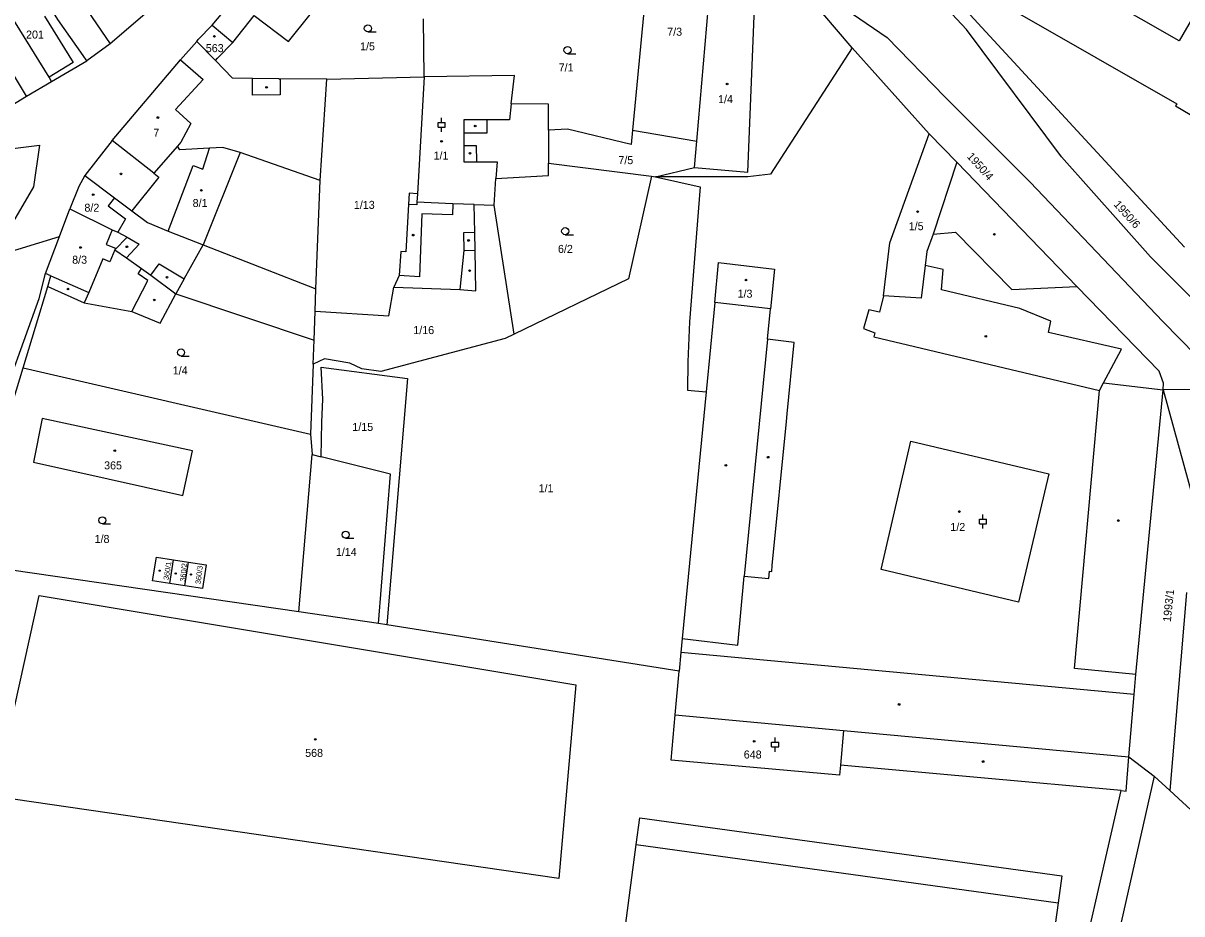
# Model space of a CAD drawing. Extents: x -794765 to -785424, y -1118958 to -1108731.
# Drawn here: x -788278.3 to -788032.3, y -1116985.8 to -1116796.6 of the extents above; entities that cross this region are included whole.
import ezdxf

# ---------------------------------------------------------------- set-up
doc = ezdxf.new("R2010")
doc.units = 0
for name, color, linetype in [('Level 66', 7, 'Continuous'), ('Level 75', 7, 'Continuous'), ('Level 76', 7, 'Continuous'), ('Level 77', 7, 'Continuous'), ('Level 79', 7, 'Continuous')]:
    doc.layers.add(name, color=color, linetype=linetype)

msp = doc.modelspace()

# ---------------------------------------------------------------- linework, layer by layer
at = {"layer": 'Level 66'}
for p, q in [((-788205.14, -1116798.45), (-788203.39, -1116798.45)), ((-788162.74, -1116803.07), (-788160.99, -1116803.07)), ((-788189.48, -1116817.69), (-788189.48, -1116816.69)), ((-788190.23, -1116817.69), (-788188.73, -1116817.69)), ((-788190.23, -1116818.69), (-788190.23, -1116817.69)), ((-788190.23, -1116818.69), (-788188.73, -1116818.69)), ((-788189.48, -1116819.69), (-788189.48, -1116818.69)), ((-788188.73, -1116818.69), (-788188.73, -1116817.69)), ((-788163.24, -1116841.52), (-788161.49, -1116841.52)), ((-788244.8, -1116867.29), (-788243.05, -1116867.29)), ((-788074.53, -1116901.92), (-788074.53, -1116900.92)), ((-788261.5, -1116902.94), (-788259.75, -1116902.94)), ((-788075.28, -1116901.92), (-788073.78, -1116901.92)), ((-788075.28, -1116902.92), (-788075.28, -1116901.92)), ((-788075.28, -1116902.92), (-788073.78, -1116902.92)), ((-788074.53, -1116903.92), (-788074.53, -1116902.92)), ((-788073.78, -1116902.92), (-788073.78, -1116901.92)), ((-788209.86, -1116905.99), (-788208.11, -1116905.99)), ((-788119.4, -1116949.33), (-788117.9, -1116949.33)), ((-788119.4, -1116950.33), (-788119.4, -1116949.33)), ((-788119.4, -1116950.33), (-788117.9, -1116950.33)), ((-788118.65, -1116949.33), (-788118.65, -1116948.33)), ((-788118.65, -1116951.33), (-788118.65, -1116950.33)), ((-788117.9, -1116950.33), (-788117.9, -1116949.33))]:
    msp.add_line(p, q, dxfattribs=at)
for centre in [(-788205.14, -1116797.7), (-788162.74, -1116802.32), (-788163.24, -1116840.77), (-788244.8, -1116866.54), (-788261.5, -1116902.19), (-788209.86, -1116905.24)]:
    msp.add_circle(centre, 0.75, dxfattribs=at)
at = {"layer": 'Level 75'}
for p, q in [((-788102.31, -1116801.86), (-788122.75, -1116777.73)), ((-788238.21, -1116796.99), (-788224.89, -1116781.19)), ((-788086.56, -1116784.66), (-788031.75, -1116844.15)), ((-788135.27, -1116821.65), (-788132.81, -1116792.93)), ((-788238.21, -1116796.99), (-788233.82, -1116800.7)), ((-788193.21, -1116808), (-788193.34, -1116795.7)), ((-788237.52, -1116804.54), (-788241.47, -1116800.45)), ((-788102.31, -1116801.86), (-788119.65, -1116828.64)), ((-788085.95, -1116820.1), (-788102.31, -1116801.86)), ((-788272.28, -1116808.99), (-788264.8, -1116804.59)), ((-788215.23, -1116830.01), (-788213.88, -1116808.51)), ((-788213.88, -1116808.51), (-788193.21, -1116808)), ((-788166.76, -1116819.32), (-788166.76, -1116826.32)), ((-788148.95, -1116819.33), (-788135.27, -1116821.65)), ((-788259.4, -1116821.53), (-788265.21, -1116828.93)), ((-788080.11, -1116826.14), (-788085.95, -1116820.1)), ((-788166.76, -1116826.32), (-788144.9, -1116829.12)), ((-788144.9, -1116829.12), (-788144.03, -1116829.23)), ((-788124.47, -1116829.22), (-788144.03, -1116829.23)), ((-788119.65, -1116828.64), (-788124.47, -1116829.22)), ((-788216.17, -1116853), (-788215.23, -1116830.01)), ((-788270.62, -1116841.89), (-788268.43, -1116836.01)), ((-788174.1, -1116862.62), (-788178.35, -1116835.27)), ((-788284.93, -1116846.27), (-788270.62, -1116841.89)), ((-788273.57, -1116849.78), (-788270.62, -1116841.89)), ((-788278.3, -1116869.83), (-788273.09, -1116852.5)), ((-788245.9, -1116854.09), (-788216.56, -1116863.93)), ((-788216.34, -1116857.79), (-788216.17, -1116853)), ((-788216.56, -1116863.93), (-788216.34, -1116857.79)), ((-788216.76, -1116869.03), (-788216.56, -1116863.93)), ((-788216.76, -1116869.03), (-788217.35, -1116883.92)), ((-788284.57, -1116890.25), (-788278.3, -1116869.83)), ((-788278.3, -1116869.83), (-788217.35, -1116883.92)), ((-788022.19, -1116874.41), (-788036.25, -1116874.48)), ((-788036.25, -1116874.48), (-788029.67, -1116898.48)), ((-788217.35, -1116883.92), (-788216.97, -1116888.2)), ((-788219.76, -1116921.65), (-788216.97, -1116888.2)), ((-788216.97, -1116888.2), (-788215.03, -1116888.69)), ((-788247.21, -1116915.61), (-788246.4, -1116910.57)), ((-788246.4, -1116910.57), (-788243.2, -1116911.06)), ((-788244, -1116916.09), (-788243.2, -1116911.06)), ((-788219.76, -1116921.65), (-788280.81, -1116912.75)), ((-788244, -1116916.09), (-788247.21, -1116915.61)), ((-788031.28, -1116917.52), (-788034.85, -1116959.6)), ((-788202.9, -1116924.1), (-788219.76, -1116921.65)), ((-788201.1, -1116924.39), (-788202.9, -1116924.1)), ((-788139.02, -1116934.24), (-788201.1, -1116924.39)), ((-788139.86, -1116943.51), (-788139.02, -1116934.24)), ((-788043.54, -1116952.39), (-788038.17, -1116956.55)), ((-788038.17, -1116956.55), (-788075.38, -1117120.72)), ((-788034.85, -1116959.6), (-788038.17, -1116956.55)), ((-788034.85, -1116959.6), (-788007.01, -1116985.23))]:
    msp.add_line(p, q, dxfattribs=at)
for points in [[(-787892.56, -1116976.99), (-787895.19, -1116981.23), (-787941.8, -1116937.65), (-788018.27, -1116866.79), (-788038.98, -1116846.21), (-788057.86, -1116825), (-788078.06, -1116797.96), (-788091.43, -1116783.54), (-788101.65, -1116776.74), (-788123.35, -1116751.89), (-788142.7, -1116729.68), (-788154.86, -1116714.68), (-788158.83, -1116708.96), (-788160.26, -1116705.12), (-788161.73, -1116697.18), (-788161.16, -1116678.39), (-788158.78, -1116640.39), (-788158.44, -1116620.71), (-788158.79, -1116611.56), (-788160.53, -1116602.53)], [(-788067.75, -1116794.03), (-788033.39, -1116813.75), (-788033.67, -1116814.13), (-788027.08, -1116818.05), (-788023.52, -1116820.1), (-788021.63, -1116816.78), (-788019.77, -1116813.56), (-788015.67, -1116816), (-788014.58, -1116816.6), (-788011.36, -1116810.96), (-788011.98, -1116810.6), (-788004.49, -1116797.7), (-788002.85, -1116798.65), (-787998.57, -1116791.26), (-788020.48, -1116778.64), (-788030.53, -1116772.85), (-788034.34, -1116779.51), (-788061.85, -1116783.73), (-788067.75, -1116794.03)], [(-788168.06, -1116778.04), (-788159.81, -1116778.04), (-788147.84, -1116782.59), (-788145.53, -1116783.68), (-788148.95, -1116819.33)], [(-788121.73, -1116777.04), (-788119.47, -1116776.79), (-788115.27, -1116779.69), (-788102.26, -1116794.62), (-788094.84, -1116799.67), (-788082.62, -1116812.27), (-788064.51, -1116830.39), (-788036.35, -1116859.97), (-788022.19, -1116874.41)], [(-788233.82, -1116800.7), (-788229.26, -1116794.99), (-788222, -1116800.45), (-788217.39, -1116794.78), (-788213.71, -1116790.33), (-788215.28, -1116789.05), (-788222.43, -1116783.12), (-788224.89, -1116781.19)], [(-788264.8, -1116804.59), (-788265.57, -1116803.49), (-788270.98, -1116795.78), (-788275.03, -1116789.24), (-788277.6, -1116785.1)], [(-788272.28, -1116808.99), (-788272.83, -1116808.09), (-788284.38, -1116789.4), (-788284.62, -1116789.01)], [(-788251.53, -1116793.83), (-788259.88, -1116800.99), (-788264.8, -1116804.59)], [(-788241.47, -1116800.45), (-788241.14, -1116800.08), (-788238.21, -1116796.99)], [(-788259.4, -1116821.53), (-788244.9, -1116804.37), (-788241.47, -1116800.45)], [(-788237.52, -1116804.54), (-788237.05, -1116804.04), (-788233.82, -1116800.7)], [(-788213.88, -1116808.51), (-788224.04, -1116808.4), (-788229.65, -1116808.33), (-788233.9, -1116808.29), (-788237.52, -1116804.54)], [(-788166.76, -1116819.32), (-788166.76, -1116813.8), (-788174.7, -1116813.74), (-788174.01, -1116807.68), (-788193.21, -1116808)], [(-788291.51, -1116815.24), (-788280.71, -1116814.03), (-788277.59, -1116812.09), (-788272.28, -1116808.99)], [(-788193.21, -1116808), (-788194.63, -1116832.82), (-788196.35, -1116832.72), (-788196.49, -1116835.08), (-788197.06, -1116845.13), (-788198.15, -1116845.07), (-788198.52, -1116850.18), (-788199.59, -1116852.67)], [(-788148.95, -1116819.33), (-788149.24, -1116822.37), (-788162.77, -1116819.14), (-788166.76, -1116819.32)], [(-788292.73, -1116825.02), (-788282.75, -1116823.53), (-788274.84, -1116822.53), (-788276.12, -1116831.38), (-788284.93, -1116846.27)], [(-788215.23, -1116830.01), (-788232.28, -1116824.04), (-788235.93, -1116822.99), (-788238.75, -1116823.13), (-788245.05, -1116823.46), (-788245.56, -1116822.72), (-788250.56, -1116828.47), (-788259.4, -1116821.53)], [(-788144.03, -1116829.23), (-788135.75, -1116827.23), (-788135.27, -1116821.65)], [(-788080.11, -1116826.14), (-788085.12, -1116841.39), (-788086.46, -1116845.07), (-788086.77, -1116848.06), (-788087.67, -1116855.03), (-788095.65, -1116854.51), (-788094.28, -1116843.27), (-788085.95, -1116820.1)], [(-788178.35, -1116835.27), (-788177.93, -1116829.59), (-788166.76, -1116828.95), (-788166.76, -1116826.32)], [(-788036.25, -1116874.48), (-788036.2, -1116873.03), (-788037.12, -1116870.51), (-788054.59, -1116852.55), (-788080.11, -1116826.14)], [(-788265.21, -1116828.93), (-788266.53, -1116831.25), (-788268.43, -1116836.01)], [(-788265.21, -1116828.93), (-788258.96, -1116833.66), (-788255.25, -1116836.42), (-788251.9, -1116838.94), (-788247.57, -1116840.74), (-788240.08, -1116843.68), (-788216.17, -1116853)], [(-788144.9, -1116829.12), (-788149.81, -1116850.87), (-788174.1, -1116862.62)], [(-788144.03, -1116829.23), (-788134.59, -1116831.38), (-788136.85, -1116860), (-788137.18, -1116868.51), (-788137.26, -1116874.52), (-788133.28, -1116874.91), (-788138.4, -1116927.32), (-788138.66, -1116930.26), (-788139.02, -1116934.24)], [(-788268.43, -1116836.01), (-788259.4, -1116840.51), (-788258.26, -1116841), (-788256.25, -1116842.01), (-788258.85, -1116844.71), (-788256.4, -1116846.45), (-788253.17, -1116848.73), (-788251.22, -1116850.11), (-788245.9, -1116854.09)], [(-788199.59, -1116852.67), (-788185.64, -1116853.16), (-788182.18, -1116853.42), (-788182.35, -1116844.81), (-788182.43, -1116841.08), (-788182.55, -1116835.11), (-788178.35, -1116835.27)], [(-788119.65, -1116857.26), (-788131.44, -1116855.91), (-788130.65, -1116847.42), (-788118.8, -1116848.84), (-788119.65, -1116857.26)], [(-788286.19, -1116895.2), (-788284.39, -1116881.3), (-788274.95, -1116855.05), (-788273.57, -1116849.78)], [(-788273.09, -1116852.5), (-788272.42, -1116850.28), (-788273.57, -1116849.78)], [(-788273.09, -1116852.5), (-788265.37, -1116855.98), (-788255.24, -1116857.8), (-788249.26, -1116860.34), (-788245.9, -1116854.09)], [(-788216.34, -1116857.79), (-788200.69, -1116858.77), (-788199.59, -1116852.67)], [(-788174.1, -1116862.62), (-788176.01, -1116863.54), (-788202.36, -1116870.59), (-788206.44, -1116870.03), (-788208.96, -1116868.79), (-788214.35, -1116867.86), (-788216.76, -1116869.03)], [(-788215.03, -1116888.69), (-788214.92, -1116881.36), (-788214.67, -1116876.45), (-788215.08, -1116869.68)], [(-788215.08, -1116869.68), (-788196.74, -1116872.03), (-788201.1, -1116924.39)], [(-788043.54, -1116952.39), (-788042.44, -1116939.2), (-788042.09, -1116934.95), (-788036.25, -1116874.48)], [(-788244.45, -1116896.91), (-788242.34, -1116887.41), (-788274.3, -1116880.57), (-788276.14, -1116889.87), (-788244.45, -1116896.91)], [(-788202.9, -1116924.1), (-788200.36, -1116892.38), (-788215.03, -1116888.69)], [(-788247.21, -1116915.61), (-788250.88, -1116915.06), (-788250.05, -1116910), (-788246.4, -1116910.57)], [(-788243.2, -1116911.06), (-788239.48, -1116911.64), (-788240.26, -1116916.65), (-788244, -1116916.09)], [(-788160.99, -1116937.11), (-788164.62, -1116978.28), (-788284.44, -1116960.86), (-788274.96, -1116918.14), (-788160.99, -1116937.11)], [(-788045.15, -1116959.61), (-788104.79, -1116954.2), (-788104.99, -1116956.34), (-788140.73, -1116953.1), (-788139.86, -1116943.51)], [(-788139.86, -1116943.51), (-788104.14, -1116946.8), (-788043.54, -1116952.39)], [(-788045.15, -1116959.61), (-788044.15, -1116959.7), (-788043.54, -1116952.39)], [(-788081.69, -1117119.18), (-788081.68, -1117119.13), (-788081.44, -1117118.1), (-788056.69, -1117010.01), (-788045.15, -1116959.61)], [(-788061.09, -1117001.82), (-788061.89, -1117007.57), (-788151.31, -1116995.05), (-788150.57, -1116989.4), (-788148.16, -1116971.04), (-788147.42, -1116965.39), (-788057.75, -1116977.69), (-788058.55, -1116983.46), (-788061.09, -1117001.82)]]:
    msp.add_lwpolyline(points, dxfattribs=at)
at = {"layer": 'Level 77'}
for p, q in [((-788032.86, -1116800.34), (-788061.85, -1116783.73)), ((-788268.37, -1116788.4), (-788259.88, -1116800.99)), ((-788273.83, -1116795.1), (-788267.74, -1116804.95)), ((-788124.43, -1116828.22), (-788123.03, -1116793.32)), ((-788030.06, -1116795.48), (-788032.86, -1116800.34)), ((-788277.59, -1116812.09), (-788284.16, -1116801.24)), ((-788267.74, -1116804.95), (-788272.83, -1116808.09)), ((-788244.9, -1116804.37), (-788240.09, -1116808.55)), ((-788240.09, -1116808.55), (-788245.95, -1116814.96)), ((-788229.6, -1116811.87), (-788229.65, -1116808.33)), ((-788224.04, -1116808.4), (-788223.76, -1116808.53)), ((-788223.76, -1116808.53), (-788223.73, -1116811.81)), ((-788223.73, -1116811.81), (-788229.6, -1116811.87)), ((-788245.95, -1116814.96), (-788242.71, -1116817.92)), ((-788174.7, -1116813.74), (-788175.08, -1116817.11)), ((-788179.87, -1116817.12), (-788184.74, -1116817.13)), ((-788184.74, -1116817.13), (-788184.74, -1116819.98)), ((-788175.08, -1116817.11), (-788179.87, -1116817.12)), ((-788179.87, -1116817.12), (-788179.87, -1116819.97)), ((-788242.71, -1116817.92), (-788244.82, -1116821.87)), ((-788179.87, -1116819.97), (-788184.74, -1116819.98)), ((-788184.74, -1116819.98), (-788184.73, -1116822.6)), ((-788244.82, -1116821.87), (-788245.56, -1116822.72)), ((-788240.15, -1116827.61), (-788238.75, -1116823.13)), ((-788232.28, -1116824.04), (-788240.08, -1116843.68)), ((-788184.73, -1116822.6), (-788182.11, -1116822.59)), ((-788184.73, -1116822.6), (-788184.73, -1116826.03)), ((-788182.11, -1116822.59), (-788182.1, -1116826.02)), ((-788247.57, -1116840.74), (-788242.2, -1116826.82)), ((-788242.2, -1116826.82), (-788240.15, -1116827.61)), ((-788184.73, -1116826.03), (-788182.1, -1116826.02)), ((-788182.1, -1116826.02), (-788177.66, -1116826.01)), ((-788177.66, -1116826.01), (-788177.93, -1116829.59)), ((-788135.75, -1116827.23), (-788124.43, -1116828.22)), ((-788249.5, -1116829.3), (-788255.25, -1116836.42)), ((-788250.56, -1116828.47), (-788249.5, -1116829.3)), ((-788258.96, -1116833.66), (-788260.28, -1116835.38)), ((-788194.73, -1116834.64), (-788194.76, -1116835.18)), ((-788194.63, -1116832.82), (-788194.73, -1116834.64)), ((-788187.1, -1116834.93), (-788194.73, -1116834.64)), ((-788260.28, -1116835.38), (-788256.6, -1116838.14)), ((-788194.76, -1116835.18), (-788196.49, -1116835.08)), ((-788193.69, -1116837.06), (-788194.14, -1116850.47)), ((-788187.2, -1116837.31), (-788193.69, -1116837.06)), ((-788187.1, -1116834.93), (-788187.2, -1116837.31)), ((-788182.55, -1116835.11), (-788187.1, -1116834.93)), ((-788256.6, -1116838.14), (-788258.26, -1116841)), ((-788259.4, -1116840.51), (-788260.68, -1116843.61)), ((-788256.25, -1116842.01), (-788253.73, -1116843.53)), ((-788182.43, -1116841.08), (-788184.85, -1116841.13)), ((-788184.85, -1116841.13), (-788184.77, -1116844.85)), ((-788085.12, -1116841.39), (-788080.34, -1116840.95)), ((-788080.34, -1116840.95), (-788068.38, -1116853.19)), ((-788260.68, -1116843.61), (-788258.73, -1116844.41)), ((-788258.73, -1116844.41), (-788258.85, -1116844.71)), ((-788253.73, -1116843.53), (-788256.4, -1116846.45)), ((-788244.14, -1116850.93), (-788240.08, -1116843.68)), ((-788261.42, -1116846.65), (-788264.35, -1116853.78)), ((-788259.9, -1116847.27), (-788261.42, -1116846.65)), ((-788258.85, -1116844.71), (-788259.9, -1116847.27)), ((-788184.77, -1116844.85), (-788185.64, -1116853.16)), ((-788184.77, -1116844.85), (-788182.35, -1116844.81)), ((-788253.93, -1116849.81), (-788253.17, -1116848.73)), ((-788251.22, -1116850.11), (-788249.43, -1116847.7)), ((-788249.43, -1116847.7), (-788244.14, -1116850.93)), ((-788082.95, -1116848.93), (-788086.77, -1116848.06)), ((-788083.34, -1116853.21), (-788082.95, -1116848.93)), ((-788272.42, -1116850.28), (-788264.35, -1116853.78)), ((-788255.24, -1116857.8), (-788251.84, -1116851.28)), ((-788251.84, -1116851.28), (-788253.93, -1116849.81)), ((-788244.14, -1116850.93), (-788245.9, -1116854.09)), ((-788194.14, -1116850.47), (-788198.52, -1116850.18)), ((-788264.35, -1116853.78), (-788265.37, -1116855.98)), ((-788095.65, -1116854.51), (-788096.48, -1116858.01)), ((-788066.7, -1116857.2), (-788083.34, -1116853.21)), ((-788068.38, -1116853.19), (-788054.59, -1116852.55)), ((-788131.44, -1116855.91), (-788133.28, -1116874.91)), ((-788120.28, -1116863.72), (-788119.65, -1116857.26)), ((-788098.79, -1116857.47), (-788099.91, -1116861.46)), ((-788096.48, -1116858.01), (-788098.79, -1116857.47)), ((-788060.09, -1116859.87), (-788066.7, -1116857.2)), ((-788099.91, -1116861.46), (-788097.51, -1116862.33)), ((-788060.65, -1116862.27), (-788060.09, -1116859.87)), ((-788120.28, -1116863.72), (-788125.21, -1116914.05)), ((-788114.64, -1116864.42), (-788120.28, -1116863.72)), ((-788097.51, -1116862.33), (-788097.72, -1116863.2)), ((-788097.72, -1116863.2), (-788049.79, -1116874.59)), ((-788045.12, -1116865.85), (-788060.65, -1116862.27)), ((-788116.12, -1116879.58), (-788114.64, -1116864.42)), ((-788048.94, -1116873), (-788045.12, -1116865.85)), ((-788049.79, -1116874.59), (-788048.94, -1116873)), ((-788048.94, -1116873), (-788036.25, -1116874.48)), ((-788055.1, -1116933.69), (-788049.79, -1116874.59)), ((-788119.27, -1116911.79), (-788116.28, -1116881.17)), ((-788116.28, -1116881.17), (-788116.12, -1116879.58)), ((-788096.15, -1116912.66), (-788089.88, -1116885.36)), ((-788089.88, -1116885.36), (-788060.56, -1116892.31)), ((-788060.56, -1116892.31), (-788066.97, -1116919.56)), ((-788119.97, -1116914.57), (-788119.89, -1116913.02)), ((-788119.89, -1116913.02), (-788119.39, -1116913.07)), ((-788119.39, -1116913.07), (-788119.27, -1116911.79)), ((-788066.97, -1116919.56), (-788096.15, -1116912.66)), ((-788126.6, -1116928.71), (-788125.21, -1116914.05)), ((-788125.21, -1116914.05), (-788119.97, -1116914.57)), ((-788138.4, -1116927.32), (-788126.6, -1116928.71)), ((-788042.44, -1116939.2), (-788138.66, -1116930.26)), ((-788042.09, -1116934.95), (-788055.1, -1116933.69)), ((-788104.14, -1116946.8), (-788104.79, -1116954.2)), ((-788148.16, -1116971.04), (-788058.55, -1116983.46))]:
    msp.add_line(p, q, dxfattribs=at)
at = {"layer": 'Level 79'}
for centre, radius in [((-788237.72, -1116799.4), 0.175), ((-788226.65, -1116810.21), 0.175), ((-788128.86, -1116809.51), 0.175), ((-788249.72, -1116816.63), 0.175), ((-788182.34, -1116818.44), 0.175), ((-788189.49, -1116821.7), 0.175), ((-788183.46, -1116824.22), 0.175), ((-788257.56, -1116828.61), 0.175), ((-788240.49, -1116832.1), 0.175), ((-788263.45, -1116833.03), 0.175), ((-788088.41, -1116836.62), 0.175), ((-788195.5, -1116841.61), 0.175), ((-788072.11, -1116841.43), 0.175), ((-788266.15, -1116844.24), 0.175), ((-788256.31, -1116844.09), 0.175), ((-788183.75, -1116842.75), 0.175), ((-788183.53, -1116849.16), 0.175), ((-788247.78, -1116850.55), 0.175), ((-788124.86, -1116851.15), 0.175), ((-788268.81, -1116853.06), 0.175), ((-788250.48, -1116855.38), 0.175), ((-788073.92, -1116863.12), 0.175), ((-788258.87, -1116887.4), 0.175), ((-788120.15, -1116888.79), 0.175), ((-788129.11, -1116890.51), 0.175), ((-788079.53, -1116900.32), 0.175), ((-788045.79, -1116902.24), 0.175), ((-788249.35, -1116912.87), 0.117), ((-788245.94, -1116913.48), 0.117), ((-788242.7, -1116913.7), 0.117), ((-788092.33, -1116941.3), 0.175), ((-788216.3, -1116948.72), 0.175), ((-788123.11, -1116949.12), 0.175), ((-788074.49, -1116953.42), 0.175)]:
    msp.add_circle(centre, radius, dxfattribs=at)

# ---------------------------------------------------------------- texts
at = {"layer": 'Level 76'}
for s, p in [('7/3', (-788141.57, -1116799.26)), ('201', (-788277.71, -1116799.86)), ('563', (-788239.55, -1116802.75)), ('1/5', (-788206.79, -1116802.36)), ('7/1', (-788164.62, -1116806.85)), ('1/4', (-788130.78, -1116813.57)), ('7', (-788250.68, -1116820.7)), ('1/1', (-788191.19, -1116825.57)), ('7/5', (-788151.94, -1116826.53)), ('8/2', (-788265.32, -1116836.64)), ('8/1', (-788242.34, -1116835.64)), ('1/13', (-788208.11, -1116836.03)), ('1/5', (-788090.29, -1116840.56)), ('6/2', (-788164.77, -1116845.39)), ('8/3', (-788267.92, -1116847.69)), ('1/3', (-788126.64, -1116854.9)), ('1/16', (-788195.49, -1116862.63)), ('1/4', (-788246.56, -1116871.2)), ('1/15', (-788208.43, -1116883.2)), ('365', (-788261.14, -1116891.37)), ('1/1', (-788168.89, -1116896.25)), ('1/2', (-788081.46, -1116904.45)), ('1/8', (-788263.16, -1116906.99)), ('1/14', (-788211.93, -1116909.75)), ('568', (-788218.45, -1116952.44)), ('648', (-788125.32, -1116952.78))]:
    msp.add_text(s, height=1.7, dxfattribs=at).set_placement(p)
for s, height, rotation, p in [('1950/4', 1.7, 312, (-788078.06, -1116824.98)), ('1950/6', 1.7, 312, (-788046.88, -1116835.18)), ('360/1', 1.14, 81, (-788247.45, -1116914.95)), ('360/2', 1.14, 84, (-788243.92, -1116915.27)), ('360/3', 1.14, 83, (-788240.66, -1116915.8)), ('1993/1', 1.7, 84, (-788034.65, -1116923.84))]:
    msp.add_text(s, height=height, rotation=rotation, dxfattribs=at).set_placement(p)

doc.saveas('drawing.dxf')
